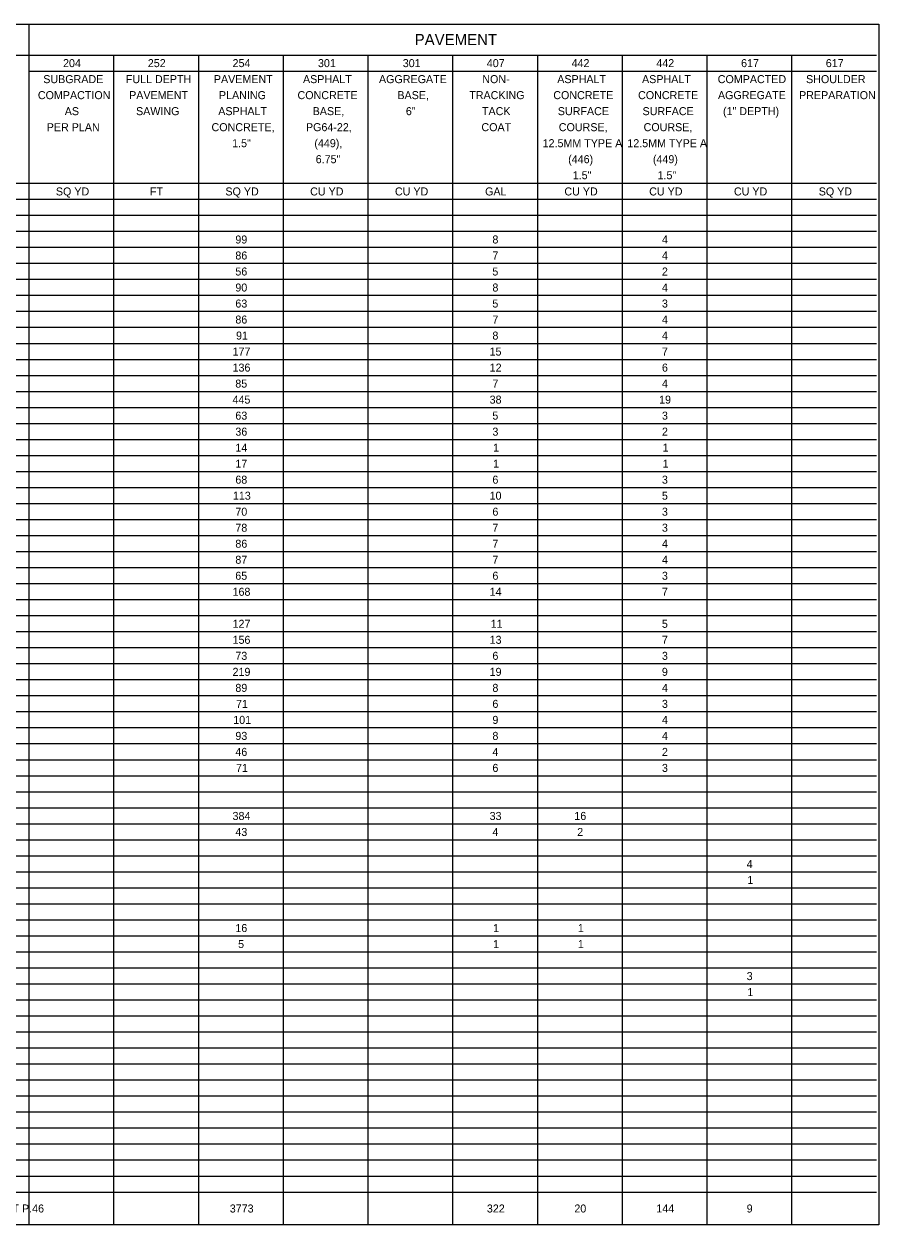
# Model space of a CAD drawing. Extents: x 12522 to 13018, y 1124 to 1902.
# Drawn here: x 12812.77 to 12827.72, y 1732.23 to 1753.23 of the extents above; entities that cross this region are included whole.
import ezdxf

# ---------------------------------------------------------------- set-up
doc = ezdxf.new("R2010")
doc.units = 0
for name, color, linetype in [('SC_Scratch1', 7, 'Continuous'), ('SH_Data', 7, 'Continuous'), ('SH_Text', 7, 'Continuous')]:
    doc.layers.add(name, color=color, linetype=linetype)

msp = doc.modelspace()

# ---------------------------------------------------------------- linework, layer by layer
at = {"layer": 'SC_Scratch1'}
msp.add_lwpolyline([(12797.224, 1753.227), (12827.724, 1753.227), (12827.724, 1732.227), (12797.224, 1732.227)], close=True, dxfattribs=at)
at = {"layer": 'SH_Data'}
for p, q in [((12812.855, 1753.227), (12812.855, 1732.227)), ((12797.224, 1752.683), (12827.678, 1752.683)), ((12814.337, 1752.683), (12814.337, 1732.227)), ((12815.82, 1752.683), (12815.82, 1732.227)), ((12817.302, 1752.683), (12817.302, 1732.227)), ((12818.784, 1752.683), (12818.784, 1732.227)), ((12820.267, 1752.683), (12820.267, 1732.227)), ((12821.749, 1752.683), (12821.749, 1732.227)), ((12823.231, 1752.683), (12823.231, 1732.227)), ((12824.714, 1752.683), (12824.714, 1732.227)), ((12826.196, 1752.683), (12826.196, 1732.227)), ((12812.855, 1752.403), (12827.678, 1752.403)), ((12806.184, 1750.443), (12827.678, 1750.443)), ((12797.224, 1750.163), (12827.678, 1750.163)), ((12797.224, 1749.883), (12827.678, 1749.883)), ((12797.224, 1749.603), (12827.678, 1749.603)), ((12797.224, 1749.323), (12827.678, 1749.323)), ((12797.224, 1749.043), (12827.678, 1749.043)), ((12797.224, 1748.763), (12827.678, 1748.763)), ((12797.224, 1748.483), (12827.678, 1748.483)), ((12797.224, 1748.203), (12827.678, 1748.203)), ((12797.224, 1747.923), (12827.678, 1747.923)), ((12797.224, 1747.643), (12827.678, 1747.643)), ((12797.224, 1747.363), (12827.678, 1747.363)), ((12797.224, 1747.083), (12827.678, 1747.083)), ((12797.224, 1746.803), (12827.678, 1746.803)), ((12797.224, 1746.523), (12827.678, 1746.523)), ((12797.224, 1746.243), (12827.678, 1746.243)), ((12797.224, 1745.963), (12827.678, 1745.963)), ((12797.224, 1745.683), (12827.678, 1745.683)), ((12797.224, 1745.403), (12827.678, 1745.403)), ((12797.224, 1745.123), (12827.678, 1745.123)), ((12797.224, 1744.843), (12827.678, 1744.843)), ((12797.224, 1744.563), (12827.678, 1744.563)), ((12797.224, 1744.283), (12827.678, 1744.283)), ((12797.224, 1744.003), (12827.678, 1744.003)), ((12797.224, 1743.723), (12827.678, 1743.723)), ((12797.224, 1743.443), (12827.678, 1743.443)), ((12797.224, 1743.163), (12827.678, 1743.163)), ((12797.224, 1742.883), (12827.678, 1742.883)), ((12797.224, 1742.603), (12827.678, 1742.603)), ((12797.224, 1742.323), (12827.678, 1742.323)), ((12797.224, 1742.043), (12827.678, 1742.043)), ((12797.224, 1741.763), (12827.678, 1741.763)), ((12797.224, 1741.483), (12827.678, 1741.483)), ((12797.224, 1741.203), (12827.678, 1741.203)), ((12797.224, 1740.923), (12827.678, 1740.923)), ((12797.224, 1740.643), (12827.678, 1740.643)), ((12797.224, 1740.363), (12827.678, 1740.363)), ((12797.224, 1740.083), (12827.678, 1740.083)), ((12797.224, 1739.803), (12827.678, 1739.803)), ((12797.224, 1739.523), (12827.678, 1739.523)), ((12797.224, 1739.243), (12827.678, 1739.243)), ((12797.224, 1738.963), (12827.678, 1738.963)), ((12797.224, 1738.683), (12827.678, 1738.683)), ((12797.224, 1738.403), (12827.678, 1738.403)), ((12797.224, 1738.123), (12827.678, 1738.123)), ((12797.224, 1737.843), (12827.678, 1737.843)), ((12797.224, 1737.563), (12827.678, 1737.563)), ((12797.224, 1737.283), (12827.678, 1737.283)), ((12797.224, 1737.003), (12827.678, 1737.003)), ((12797.224, 1736.723), (12827.678, 1736.723)), ((12797.224, 1736.443), (12827.678, 1736.443)), ((12797.224, 1736.163), (12827.678, 1736.163)), ((12797.224, 1735.883), (12827.678, 1735.883)), ((12797.224, 1735.603), (12827.678, 1735.603)), ((12797.224, 1735.323), (12827.678, 1735.323)), ((12797.224, 1735.043), (12827.678, 1735.043)), ((12797.224, 1734.763), (12827.678, 1734.763)), ((12797.224, 1734.483), (12827.678, 1734.483)), ((12797.224, 1734.203), (12827.678, 1734.203)), ((12797.224, 1733.923), (12827.678, 1733.923)), ((12797.224, 1733.643), (12827.678, 1733.643)), ((12797.224, 1733.363), (12827.678, 1733.363)), ((12797.224, 1733.083), (12827.678, 1733.083)), ((12797.224, 1732.803), (12827.678, 1732.803))]:
    msp.add_line(p, q, dxfattribs=at)

# ---------------------------------------------------------------- texts
at = {"layer": 'SH_Text'}
for s, height, p in [('PAVEMENT', 0.196, (12819.603, 1752.857)), ('204', 0.14, (12813.453, 1752.473)), ('252', 0.14, (12814.936, 1752.473)), ('254', 0.14, (12816.418, 1752.473)), ('301', 0.14, (12817.912, 1752.473)), ('301', 0.14, (12819.395, 1752.473)), ('407', 0.14, (12820.865, 1752.473)), ('442', 0.14, (12822.348, 1752.473)), ('442', 0.14, (12823.83, 1752.473)), ('617', 0.14, (12825.312, 1752.473)), ('617', 0.14, (12826.794, 1752.473)), ('SUBGRADE', 0.14, (12813.107, 1752.193)), ('FULL DEPTH', 0.14, (12814.551, 1752.193)), ('PAVEMENT', 0.14, (12816.091, 1752.193)), ('ASPHALT', 0.14, (12817.65, 1752.193)), ('AGGREGATE', 0.14, (12818.979, 1752.193)), ('NON-', 0.14, (12820.786, 1752.193)), ('ASPHALT', 0.14, (12822.097, 1752.193)), ('ASPHALT', 0.14, (12823.58, 1752.193)), ('COMPACTED', 0.14, (12824.904, 1752.193)), ('SHOULDER', 0.14, (12826.449, 1752.193)), ('COMPACTION', 0.14, (12813.013, 1751.913)), ('PAVEMENT', 0.14, (12814.609, 1751.913)), ('PLANING', 0.14, (12816.18, 1751.913)), ('CONCRETE', 0.14, (12817.554, 1751.913)), (' BASE,', 0.14, (12819.249, 1751.913)), ('TRACKING', 0.14, (12820.558, 1751.913)), (' CONCRETE', 0.14, (12821.976, 1751.913)), (' CONCRETE', 0.14, (12823.459, 1751.913)), ('AGGREGATE', 0.14, (12824.908, 1751.913)), ('PREPARATION', 0.14, (12826.326, 1751.913)), ('AS', 0.14, (12813.483, 1751.633)), ('SAWING', 0.14, (12814.73, 1751.633)), ('ASPHALT', 0.14, (12816.168, 1751.633)), (' BASE,', 0.14, (12817.767, 1751.633)), ('6"', 0.14, (12819.449, 1751.633)), ('TACK', 0.14, (12820.78, 1751.633)), (' SURFACE', 0.14, (12822.055, 1751.633)), (' SURFACE', 0.14, (12823.537, 1751.633)), ('(1" DEPTH)', 0.14, (12824.996, 1751.633)), ('PER PLAN', 0.14, (12813.168, 1751.353)), ('CONCRETE,', 0.14, (12816.05, 1751.353)), (' PG64-22,', 0.14, (12817.65, 1751.353)), ('COAT', 0.14, (12820.771, 1751.353)), (' COURSE,', 0.14, (12822.072, 1751.353)), (' COURSE,', 0.14, (12823.555, 1751.353)), ('1.5"', 0.14, (12816.411, 1751.073)), (' (449),', 0.14, (12817.797, 1751.073)), ('12.5MM TYPE A', 0.14, (12821.841, 1751.073)), ('12.5MM TYPE A', 0.14, (12823.323, 1751.073)), (' 6.75"', 0.14, (12817.82, 1750.793)), ('(446)', 0.14, (12822.288, 1750.793)), ('(449)', 0.14, (12823.77, 1750.793)), (' 1.5"', 0.14, (12822.316, 1750.513)), (' 1.5"', 0.14, (12823.799, 1750.513)), ('SQ YD', 0.14, (12813.328, 1750.229)), ('FT', 0.14, (12814.973, 1750.229)), ('SQ YD', 0.14, (12816.293, 1750.229)), ('CU YD', 0.14, (12817.775, 1750.229)), ('CU YD', 0.14, (12819.258, 1750.229)), ('GAL', 0.14, (12820.835, 1750.229)), ('CU YD', 0.14, (12822.222, 1750.229)), ('CU YD', 0.14, (12823.705, 1750.229)), ('CU YD', 0.14, (12825.187, 1750.229)), ('SQ YD', 0.14, (12826.67, 1750.229)), ('99', 0.14, (12816.467, 1749.389)), ('8', 0.14, (12820.963, 1749.389)), ('4', 0.14, (12823.928, 1749.389)), ('86', 0.14, (12816.467, 1749.109)), ('7', 0.14, (12820.963, 1749.109)), ('4', 0.14, (12823.928, 1749.109)), ('56', 0.14, (12816.467, 1748.829)), ('5', 0.14, (12820.962, 1748.829)), ('2', 0.14, (12823.928, 1748.829)), ('90', 0.14, (12816.467, 1748.549)), ('8', 0.14, (12820.963, 1748.549)), ('4', 0.14, (12823.928, 1748.549)), ('63', 0.14, (12816.467, 1748.269)), ('5', 0.14, (12820.962, 1748.269)), ('3', 0.14, (12823.928, 1748.269)), ('86', 0.14, (12816.467, 1747.989)), ('7', 0.14, (12820.963, 1747.989)), ('4', 0.14, (12823.928, 1747.989)), ('91', 0.14, (12816.479, 1747.709)), ('8', 0.14, (12820.963, 1747.709)), ('4', 0.14, (12823.928, 1747.709)), ('177', 0.14, (12816.418, 1747.429)), ('15', 0.14, (12820.913, 1747.429)), ('7', 0.14, (12823.928, 1747.429)), ('136', 0.14, (12816.418, 1747.149)), ('12', 0.14, (12820.915, 1747.149)), ('6', 0.14, (12823.928, 1747.149)), ('85', 0.14, (12816.466, 1746.869)), ('7', 0.14, (12820.963, 1746.869)), ('4', 0.14, (12823.928, 1746.869)), ('445', 0.14, (12816.417, 1746.589)), ('38', 0.14, (12820.914, 1746.589)), ('19', 0.14, (12823.878, 1746.589)), ('63', 0.14, (12816.467, 1746.309)), ('5', 0.14, (12820.962, 1746.309)), ('3', 0.14, (12823.928, 1746.309)), ('36', 0.14, (12816.467, 1746.029)), ('3', 0.14, (12820.963, 1746.029)), ('2', 0.14, (12823.928, 1746.029)), ('14', 0.14, (12816.467, 1745.749)), ('1', 0.14, (12820.975, 1745.749)), ('1', 0.14, (12823.94, 1745.749)), ('17', 0.14, (12816.467, 1745.469)), ('1', 0.14, (12820.975, 1745.469)), ('1', 0.14, (12823.94, 1745.469)), ('68', 0.14, (12816.467, 1745.189)), ('6', 0.14, (12820.963, 1745.189)), ('3', 0.14, (12823.928, 1745.189)), ('113', 0.14, (12816.424, 1744.909)), ('10', 0.14, (12820.914, 1744.909)), ('5', 0.14, (12823.927, 1744.909)), ('70', 0.14, (12816.467, 1744.629)), ('6', 0.14, (12820.963, 1744.629)), ('3', 0.14, (12823.928, 1744.629)), ('78', 0.14, (12816.467, 1744.349)), ('7', 0.14, (12820.963, 1744.349)), ('3', 0.14, (12823.928, 1744.349)), ('86', 0.14, (12816.467, 1744.069)), ('7', 0.14, (12820.963, 1744.069)), ('4', 0.14, (12823.928, 1744.069)), ('87', 0.14, (12816.467, 1743.789)), ('7', 0.14, (12820.963, 1743.789)), ('4', 0.14, (12823.928, 1743.789)), ('65', 0.14, (12816.466, 1743.509)), ('6', 0.14, (12820.963, 1743.509)), ('3', 0.14, (12823.928, 1743.509)), ('168', 0.14, (12816.418, 1743.229)), ('14', 0.14, (12820.914, 1743.229)), ('7', 0.14, (12823.928, 1743.229)), ('127', 0.14, (12816.418, 1742.669)), ('11', 0.14, (12820.933, 1742.669)), ('5', 0.14, (12823.927, 1742.669)), ('156', 0.14, (12816.418, 1742.389)), ('13', 0.14, (12820.914, 1742.389)), ('7', 0.14, (12823.928, 1742.389)), ('73', 0.14, (12816.467, 1742.109)), ('6', 0.14, (12820.963, 1742.109)), ('3', 0.14, (12823.928, 1742.109)), ('219', 0.14, (12816.418, 1741.829)), ('19', 0.14, (12820.914, 1741.829)), ('9', 0.14, (12823.927, 1741.829)), ('89', 0.14, (12816.467, 1741.549)), ('8', 0.14, (12820.963, 1741.549)), ('4', 0.14, (12823.928, 1741.549)), ('71', 0.14, (12816.479, 1741.269)), ('6', 0.14, (12820.963, 1741.269)), ('3', 0.14, (12823.928, 1741.269)), ('101', 0.14, (12816.43, 1740.989)), ('9', 0.14, (12820.963, 1740.989)), ('4', 0.14, (12823.928, 1740.989)), ('93', 0.14, (12816.467, 1740.709)), ('8', 0.14, (12820.963, 1740.709)), ('4', 0.14, (12823.928, 1740.709)), ('46', 0.14, (12816.467, 1740.429)), ('4', 0.14, (12820.963, 1740.429)), ('2', 0.14, (12823.928, 1740.429)), ('71', 0.14, (12816.479, 1740.149)), ('6', 0.14, (12820.963, 1740.149)), ('3', 0.14, (12823.928, 1740.149)), ('384', 0.14, (12816.418, 1739.309)), ('33', 0.14, (12820.914, 1739.309)), ('16', 0.14, (12822.396, 1739.309)), ('43', 0.14, (12816.467, 1739.029)), ('4', 0.14, (12820.963, 1739.029)), ('2', 0.14, (12822.446, 1739.029)), ('4', 0.14, (12825.41, 1738.469)), ('1', 0.14, (12825.422, 1738.189)), ('16', 0.14, (12816.467, 1737.349)), ('1', 0.14, (12820.975, 1737.349)), ('1', 0.14, (12822.457, 1737.349)), ('5', 0.14, (12816.515, 1737.069)), ('1', 0.14, (12820.975, 1737.069)), ('1', 0.14, (12822.457, 1737.069)), ('3', 0.14, (12825.41, 1736.509)), ('1', 0.14, (12825.422, 1736.229)), ('TOTALS CARRIED TO PAVEMENT SUBSUMMARY SHEET P.46', 0.14, (12807.597, 1732.445)), ('3773', 0.14, (12816.369, 1732.445)), ('322', 0.14, (12820.866, 1732.445)), ('20', 0.14, (12822.396, 1732.445)), ('144', 0.14, (12823.83, 1732.445)), ('9', 0.14, (12825.41, 1732.445))]:
    msp.add_text(s, height=height, dxfattribs=at).set_placement(p)

doc.saveas('drawing.dxf')
